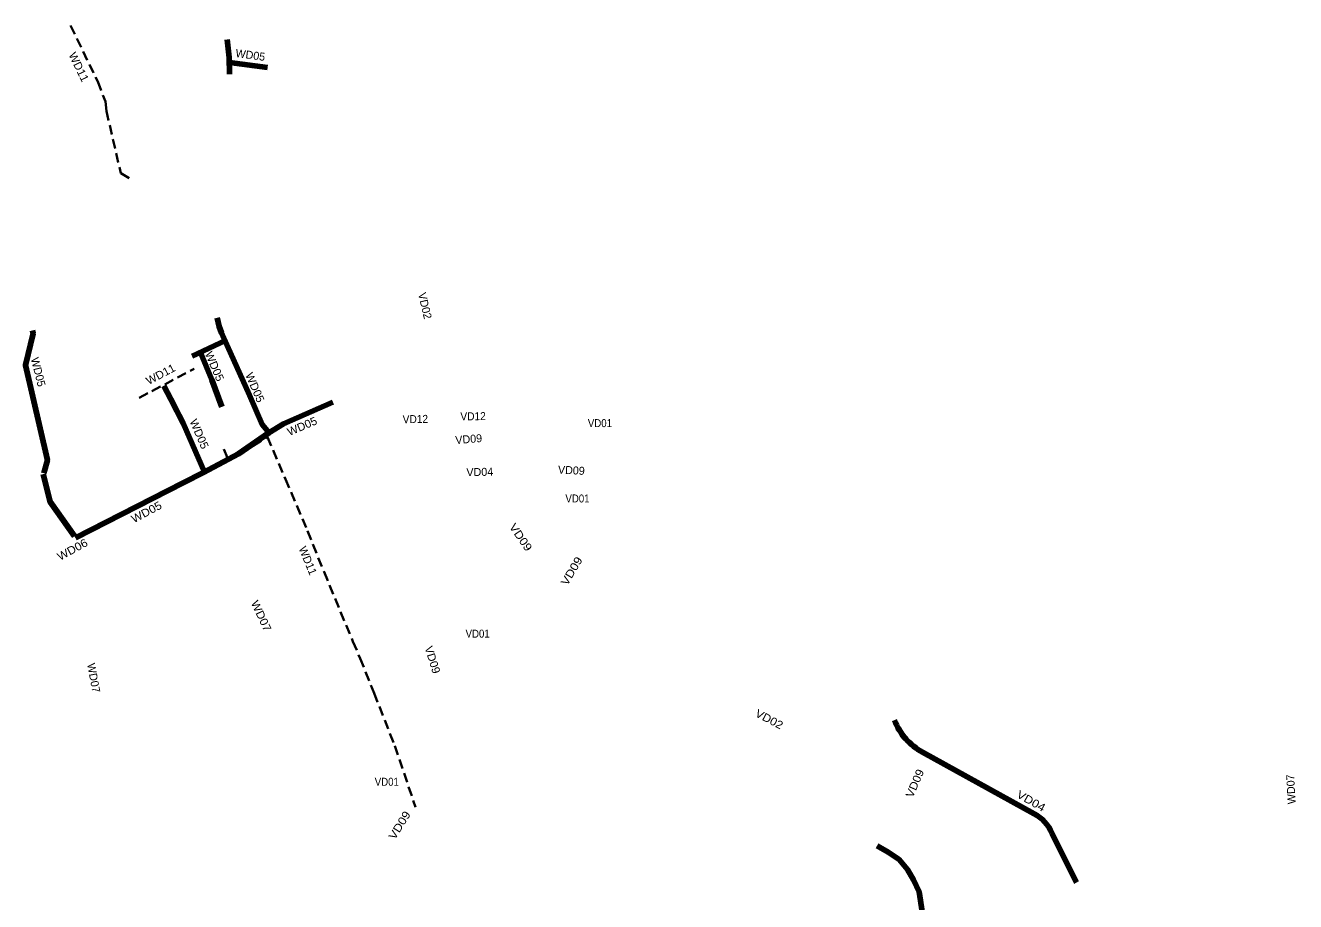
# Model space of a CAD drawing. Extents: x -650082 to -644047, y -1073232 to -1066669.
# Drawn here: x -648760 to -645586, y -1068858 to -1066669 of the extents above; entities that cross this region are included whole.
import ezdxf

# ---------------------------------------------------------------- set-up
doc = ezdxf.new("R2010")
doc.units = 0
doc.header["$LTSCALE"] = 8
doc.linetypes.add('MEDIUM_DASHED', pattern=[4.5, 3, -1.5])
for name, color, linetype in [('1', 7, 'Continuous'), ('14', 7, 'Continuous'), ('15', 7, 'Continuous'), ('2', 7, 'Continuous'), ('20', 7, 'Continuous'), ('4', 7, 'Continuous'), ('5', 7, 'Continuous'), ('6', 7, 'Continuous'), ('7', 7, 'Continuous'), ('9', 7, 'Continuous')]:
    doc.layers.add(name, color=color, linetype=linetype)
for name, color, linetype, lineweight in [('11', 7, 'Continuous', 106), ('13', 7, 'MEDIUM_DASHED', 35), ('47', 7, 'Continuous', 106), ('48', 7, 'Continuous', 106)]:
    doc.layers.add(name, color=color, linetype=linetype, lineweight=lineweight)

msp = doc.modelspace()

# ---------------------------------------------------------------- linework, layer by layer
at = {"layer": '11'}
for p, q in [((-646518.278, -1068484.783), (-646239.17, -1068638.65)), ((-646195.455, -1068687.016), (-646134.093, -1068810.478))]:
    msp.add_line(p, q, dxfattribs=at)
msp.add_lwpolyline([(-646581.274, -1069162.086), (-646543.734, -1069031.454), (-646526.307, -1068970.81), (-646520.034, -1068926.895), (-646519.124, -1068882.525), (-646527.13, -1068833.717), (-646541.089, -1068803.463), (-646555.823, -1068777.863), (-646576.76, -1068753.039), (-646603.929, -1068734.295), (-646632.204, -1068718.474)], dxfattribs=at)
for centre, radius, start, end in [((-646447.332, -1068351.964), 150.58, 200.6496, 241.891), ((-646287.447, -1068726.224), 100, 23.08426, 61.13296)]:
    msp.add_arc(centre, radius, start, end, dxfattribs=at)
at = {"layer": '13'}
msp.add_line((-648475.967, -1067599.594), (-648338.66, -1067527.2), dxfattribs=at)
for points in [[(-648647.496, -1066669.346), (-648579.736, -1066809.705), (-648560.474, -1066859.378), (-648557.753, -1066883.158), (-648521.948, -1067038.793), (-648497.158, -1067053.043)], [(-648264.598, -1067727.614), (-648252.736, -1067757.259), (-648155.436, -1067697.673), (-648110.6, -1067802.59), (-648055.22, -1067932.18), (-648014.17, -1068034.51), (-647986.62, -1068101.02), (-647941.71, -1068208.14), (-647923.95, -1068250.62), (-647888.92, -1068337.51), (-647837.19, -1068468.84), (-647785.355, -1068622.544)]]:
    msp.add_lwpolyline(points, dxfattribs=at)
at = {"layer": '47'}
msp.add_line((-648250.646, -1066761.805), (-648155.644, -1066774.286), dxfattribs=at)
for points in [[(-648255.756, -1066704.635), (-648250.791, -1066749.246), (-648250.308, -1066790.948)], [(-648280.799, -1067399.829), (-648276.458, -1067421.144), (-648270.075, -1067437.427), (-648264.51, -1067450.68), (-648249.006, -1067485.873), (-648200.759, -1067593.281), (-648168.435, -1067666.153), (-648150.996, -1067687.099)], [(-648742.866, -1067431.082), (-648741.14, -1067439.225), (-648760.37, -1067518.466), (-648705.539, -1067755.758), (-648713.989, -1067787.686)], [(-648414.419, -1067569.399), (-648397.13, -1067602.97), (-648382.03, -1067632.31), (-648376.02, -1067643.98), (-648366.45, -1067662.56), (-648312.613, -1067785.188)], [(-648635.024, -1067949.253), (-648365.832, -1067812.108), (-648315.36, -1067786.394), (-648228.068, -1067739.85), (-648151.632, -1067687.45), (-648115.068, -1067664.278), (-647992.06, -1067610.462)], [(-648715.867, -1067790.503), (-648698.498, -1067859.523), (-648637.584, -1067945.635)]]:
    msp.add_lwpolyline(points, dxfattribs=at)
at = {"layer": '48'}
msp.add_line((-648259.922, -1067456.165), (-648343.313, -1067495.831), dxfattribs=at)
msp.add_lwpolyline([(-648322.534, -1067486.274), (-648294.884, -1067554.99), (-648269.579, -1067622.5)], dxfattribs=at)

# ---------------------------------------------------------------- texts
at = {"layer": '1', "width": 0.9}
for p in [(-647354.73, -1067672.938), (-647410.82, -1067861.136), (-647660.302, -1068198.804), (-647887.323, -1068568.836)]:
    msp.add_text('VD01', height=20, rotation=0.083, dxfattribs=at).set_placement(p)
at = {"layer": '14', "width": 1.05}
for rotation, p in [(295.942, (-648653.093, -1066742.467)), (27.775, (-648452.389, -1067567.821))]:
    msp.add_text('WD11', height=20, rotation=rotation, dxfattribs=at).set_placement(p)
at = {"layer": '14'}
msp.add_text('WD11', height=20, rotation=292.311, dxfattribs=at).set_placement((-648077.911, -1067975.767))
at = {"layer": '15', "width": 1.05}
msp.add_text('WD05', height=20, rotation=293.365, dxfattribs=at).set_placement((-648312.364, -1067489.016))
at = {"layer": '2'}
msp.add_text('VD02', height=20, rotation=283.284, dxfattribs=at).set_placement((-647779.255, -1067339.494))
at = {"layer": '2', "width": 1.1}
msp.add_text('VD02', height=20, rotation=332.288, dxfattribs=at).set_placement((-646938.71, -1068394.329))
at = {"layer": '20', "width": 0.95}
for p in [(-647817.467, -1067663.258), (-647673.194, -1067656.199)]:
    msp.add_text('VD12', height=20, rotation=0.939, dxfattribs=at).set_placement(p)
at = {"layer": '4'}
msp.add_text('VD04', height=20, rotation=1.14, dxfattribs=at).set_placement((-647658.076, -1067795.501))
at = {"layer": '4', "width": 1.15}
msp.add_text('VD04', height=20, rotation=330.29, dxfattribs=at).set_placement((-646285.411, -1068596.436))
at = {"layer": '5'}
for rotation, p in [(352.056, (-648236.269, -1066747.9)), (284.099, (-648747.005, -1067501.574))]:
    msp.add_text('WD05', height=20, rotation=rotation, dxfattribs=at).set_placement(p)
for rotation, width, p in [(293.365, 1.05, (-648211.332, -1067541.923)), (293.365, 1.05, (-648350.624, -1067658.036)), (23.241, 1.05, (-648100.74, -1067695.188)), (27.999, 1.1, (-648489.178, -1067912.995))]:
    msp.add_text('WD05', height=20, rotation=rotation, dxfattribs=dict(at, width=width)).set_placement(p)
at = {"layer": '6', "width": 1.1}
msp.add_text('WD06', height=20, rotation=28.611, dxfattribs=at).set_placement((-648673.978, -1068006.987))
at = {"layer": '7', "width": 1.1}
msp.add_text('WD07', height=20, rotation=295.111, dxfattribs=at).set_placement((-648197.555, -1068111.736))
at = {"layer": '7'}
for rotation, p in [(280.588, (-648606.359, -1068264.679)), (93.043, (-645585.871, -1068614.132))]:
    msp.add_text('WD07', height=20, rotation=rotation, dxfattribs=at).set_placement(p)
at = {"layer": '9'}
for rotation, p in [(4.598, (-647685.156, -1067715.389)), (356.921, (-647429.913, -1067788.745))]:
    msp.add_text('VD09', height=20, rotation=rotation, dxfattribs=at).set_placement(p)
for rotation, width, p in [(304.68, 1.15, (-647552.617, -1067922.041)), (59.386, 1.15, (-647406.292, -1068070.573)), (287.301, 1.05, (-647762.827, -1068223.473)), (66.391, 1.1, (-646543.229, -1068600.337)), (58.192, 1.15, (-647837.113, -1068705.38))]:
    msp.add_text('VD09', height=20, rotation=rotation, dxfattribs=dict(at, width=width)).set_placement(p)

doc.saveas('drawing.dxf')
